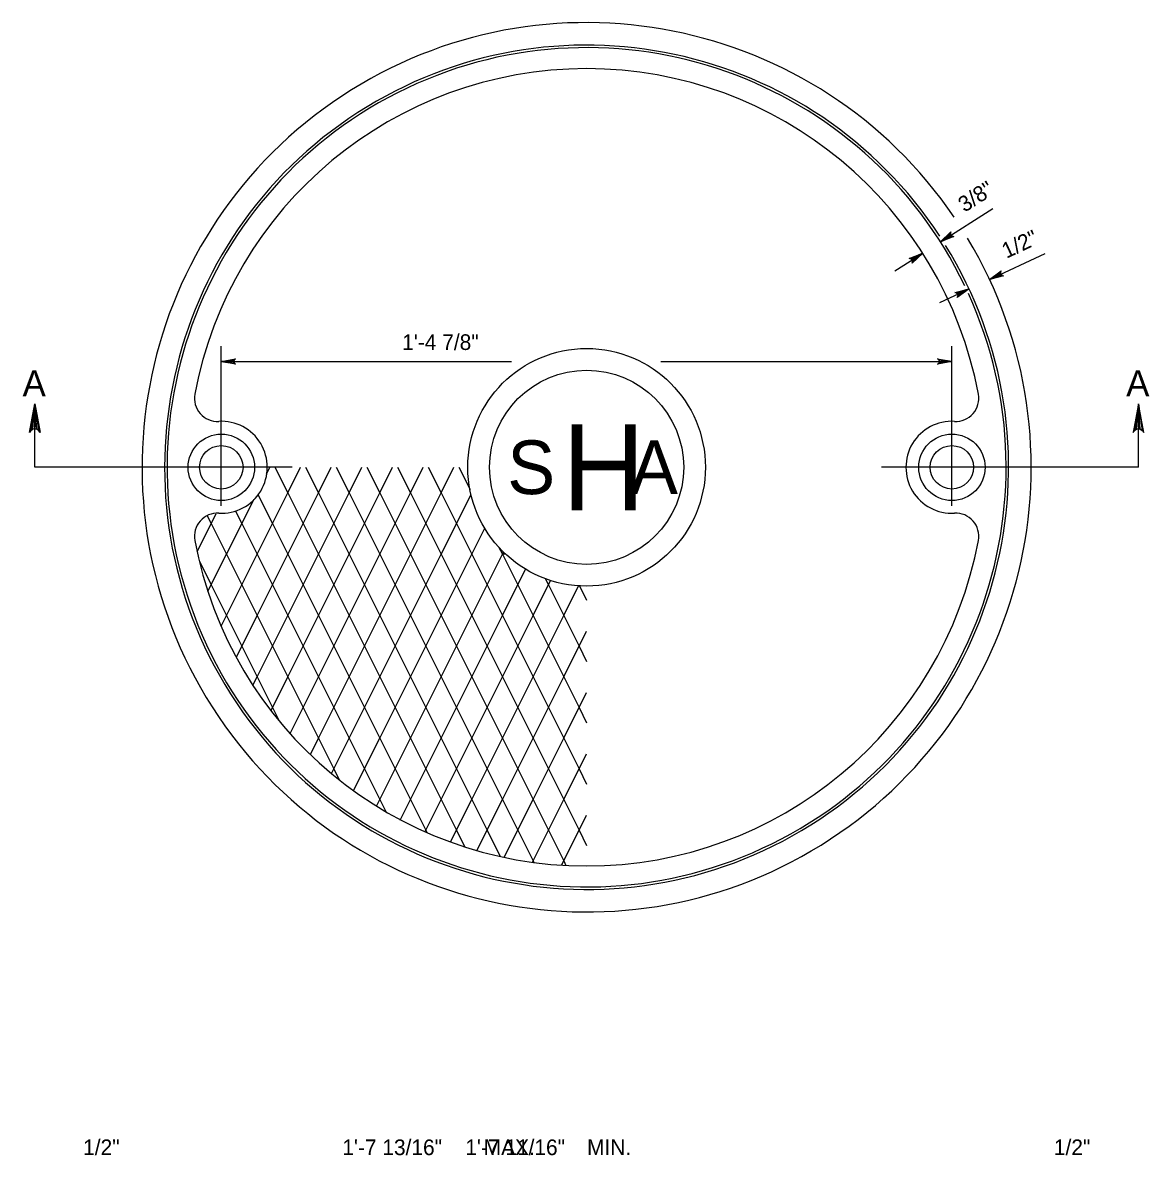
# Model space of a CAD drawing. Extents: x 2.36 to 8.41, y -8.97 to 0.21.
# Drawn here: x 2.563 to 6.887, y -4.133 to 0.213 of the extents above; entities that cross this region are included whole.
import ezdxf

# ---------------------------------------------------------------- set-up
doc = ezdxf.new("R2010")
doc.units = 0
for name, color, linetype in [('DETL-DIMS', 7, 'Continuous'), ('DETL-LINE', 7, 'Continuous'), ('DETL-NOTE', 7, 'Continuous'), ('DETL-PATT', 7, 'Continuous')]:
    doc.layers.add(name, color=color, linetype=linetype)

msp = doc.modelspace()

# ---------------------------------------------------------------- linework, layer by layer
at = {"layer": 'DETL-DIMS'}
for p, q in [((6.0855, -0.628), (6.2865, -0.5)), ((5.9113, -0.739), (6.0177, -0.6712)), ((6.2739, -0.772), (6.4871, -0.6725)), ((6.084, -0.8605), (6.1955, -0.8085)), ((3.3259, -1.6412), (3.3259, -1.0281)), ((6.1298, -1.6412), (6.1298, -1.0281)), ((3.3259, -1.087), (4.4391, -1.087)), ((5.0126, -1.087), (6.1298, -1.087)), ((2.6102, -1.4929), (2.6102, -1.25)), ((6.8455, -1.4929), (6.8455, -1.25)), ((3.5984, -1.4929), (2.6102, -1.4929)), ((6.8455, -1.4929), (5.8598, -1.4929))]:
    msp.add_line(p, q, dxfattribs=at)
for points in [[(6.0855, -0.628), (6.1262, -0.5899), (6.1242, -0.5946), (6.1243, -0.5989), (6.1258, -0.6023), (6.1283, -0.6051), (6.1321, -0.607), (6.1372, -0.6072), (6.0855, -0.628), (6.1321, -0.607), (6.1283, -0.6051), (6.0855, -0.628), (6.1258, -0.6023), (6.1243, -0.5989), (6.0855, -0.628), (6.1242, -0.5946)], [(6.0177, -0.6712), (5.977, -0.7093), (5.979, -0.7045), (5.9789, -0.7003), (5.9774, -0.6968), (5.9749, -0.6941), (5.9711, -0.6921), (5.966, -0.6919), (6.0177, -0.6712), (5.9711, -0.6921), (5.9749, -0.6941), (6.0177, -0.6712), (5.9774, -0.6968), (5.9789, -0.7003), (6.0177, -0.6712), (5.979, -0.7045)], [(6.2739, -0.772), (6.3192, -0.7395), (6.3167, -0.7439), (6.3162, -0.7482), (6.3172, -0.7518), (6.3193, -0.7548), (6.3229, -0.7572), (6.3279, -0.7581), (6.2739, -0.772), (6.3229, -0.7572), (6.3193, -0.7548), (6.2739, -0.772), (6.3172, -0.7518), (6.3162, -0.7482), (6.2739, -0.772), (6.3167, -0.7439)], [(6.1955, -0.8085), (6.1501, -0.841), (6.1527, -0.8366), (6.1531, -0.8323), (6.1522, -0.8287), (6.15, -0.8257), (6.1465, -0.8233), (6.1414, -0.8224), (6.1955, -0.8085), (6.1465, -0.8233), (6.15, -0.8257), (6.1955, -0.8085), (6.1522, -0.8287), (6.1531, -0.8323), (6.1955, -0.8085), (6.1527, -0.8366)], [(3.3259, -1.087), (3.3807, -1.0767), (3.3765, -1.0796), (3.3743, -1.0833), (3.3737, -1.087), (3.3743, -1.0906), (3.3765, -1.0943), (3.3807, -1.0972), (3.3259, -1.087), (3.3765, -1.0943), (3.3743, -1.0906), (3.3259, -1.087), (3.3737, -1.087), (3.3743, -1.0833), (3.3259, -1.087), (3.3765, -1.0796)], [(6.1298, -1.087), (6.075, -1.0972), (6.0792, -1.0943), (6.0814, -1.0906), (6.082, -1.087), (6.0814, -1.0833), (6.0792, -1.0796), (6.075, -1.0767), (6.1298, -1.087), (6.0792, -1.0796), (6.0814, -1.0833), (6.1298, -1.087), (6.082, -1.087), (6.0814, -1.0906), (6.1298, -1.087), (6.0792, -1.0943)], [(2.6102, -1.25), (2.6308, -1.3596), (2.6249, -1.3512), (2.6175, -1.3468), (2.6102, -1.3456), (2.6028, -1.3468), (2.5955, -1.3512), (2.5896, -1.3596), (2.6102, -1.25), (2.5955, -1.3512), (2.6028, -1.3468), (2.6102, -1.25), (2.6102, -1.3456), (2.6175, -1.3468), (2.6102, -1.25), (2.6249, -1.3512)], [(6.8455, -1.25), (6.8249, -1.3596), (6.8308, -1.3512), (6.8381, -1.3468), (6.8455, -1.3456), (6.8528, -1.3468), (6.8602, -1.3512), (6.8661, -1.3596), (6.8455, -1.25), (6.8602, -1.3512), (6.8528, -1.3468), (6.8455, -1.25), (6.8455, -1.3456), (6.8381, -1.3468), (6.8455, -1.25), (6.8308, -1.3512)]]:
    msp.add_lwpolyline(points, dxfattribs=at)
at = {"layer": 'DETL-LINE'}
for centre, radius in [((4.7278, -1.4929), 0.4559), ((4.7278, -1.4929), 0.3725), ((3.3259, -1.4929), 0.1275), ((6.1298, -1.4929), 0.1275), ((3.3259, -1.4929), 0.0833), ((6.1298, -1.4929), 0.0833)]:
    msp.add_circle(centre, radius, dxfattribs=at)
for centre, radius, start, end in [((4.7278, -1.4929), 1.7059, 34.2067, 31.0349), ((4.7278, -1.4929), 1.6194, 33.1799, 31.7212), ((4.7278, -1.4929), 1.6097, 25.6326, 24.4561), ((4.7278, -1.4929), 1.5294, 10.5671, 169.4329), ((3.3111, -1.2286), 0.0882, 169.4329, 273.1996), ((6.1446, -1.2286), 0.0882, 266.8004, 10.5671), ((3.3259, -1.4929), 0.1765, 266.8004, 93.1996), ((6.1298, -1.4929), 0.1765, 86.8004, 273.1996), ((3.3111, -1.7572), 0.0882, 86.8004, 190.5671), ((6.1446, -1.7572), 0.0882, 349.4329, 93.1996), ((4.7278, -1.4929), 1.5294, 190.5671, 349.4329)]:
    msp.add_arc(centre, radius, start, end, dxfattribs=at)
at = {"layer": 'DETL-PATT'}
for p, q in [((3.4996, -1.519), (3.5126, -1.4929)), ((3.5319, -1.4929), (3.5811, -1.5912)), ((3.5811, -1.5912), (3.6303, -1.4929)), ((3.6496, -1.4929), (3.6988, -1.5912)), ((3.6988, -1.5912), (3.7479, -1.4929)), ((3.7672, -1.4929), (3.8164, -1.5912)), ((3.8164, -1.5912), (3.8656, -1.4929)), ((3.8849, -1.4929), (3.934, -1.5912)), ((3.934, -1.5912), (3.9832, -1.4929)), ((4.0025, -1.4929), (4.0517, -1.5912)), ((4.0517, -1.5912), (4.1008, -1.4929)), ((4.1202, -1.4929), (4.1693, -1.5912)), ((4.1693, -1.5912), (4.2185, -1.4929)), ((4.2378, -1.4929), (4.2805, -1.5782)), ((3.4635, -1.8265), (3.5811, -1.5912)), ((3.4665, -1.5974), (3.5223, -1.7089)), ((3.5811, -1.8265), (3.6988, -1.5912)), ((3.5811, -1.5912), (3.6399, -1.7089)), ((3.6988, -1.8265), (3.8164, -1.5912)), ((3.6988, -1.5912), (3.7576, -1.7089)), ((3.8164, -1.8265), (3.934, -1.5912)), ((3.8164, -1.5912), (3.8752, -1.7089)), ((3.934, -1.8265), (4.0517, -1.5912)), ((3.934, -1.5912), (3.9929, -1.7089)), ((4.0517, -1.8265), (4.1693, -1.5912)), ((4.0517, -1.5912), (4.1105, -1.7089)), ((4.1693, -1.5912), (4.2282, -1.7089)), ((4.1693, -1.8265), (4.2842, -1.5968)), ((3.3458, -1.8265), (3.4516, -1.6148)), ((3.2335, -1.8158), (3.3057, -1.6714)), ((3.2719, -1.6788), (3.287, -1.7089)), ((3.3796, -1.6588), (3.4046, -1.7089)), ((3.287, -1.7089), (3.3458, -1.8265)), ((3.4046, -1.7089), (3.4635, -1.8265)), ((3.5223, -1.7089), (3.5811, -1.8265)), ((3.6399, -1.7089), (3.6988, -1.8265)), ((3.7576, -1.7089), (3.8164, -1.8265)), ((3.8752, -1.7089), (3.934, -1.8265)), ((3.9929, -1.7089), (4.0517, -1.8265)), ((4.1105, -1.7089), (4.1693, -1.8265)), ((4.2282, -1.7089), (4.287, -1.8265)), ((4.287, -1.8265), (4.3372, -1.726)), ((4.3915, -1.8003), (4.4046, -1.8265)), ((4.4046, -1.8265), (4.409, -1.8177)), ((3.2416, -1.8534), (3.287, -1.9442)), ((3.2748, -1.9685), (3.3458, -1.8265)), ((3.3458, -2.0618), (3.4635, -1.8265)), ((3.3458, -1.8265), (3.4046, -1.9442)), ((3.4635, -2.0618), (3.5811, -1.8265)), ((3.4635, -1.8265), (3.5223, -1.9442)), ((3.5811, -2.0618), (3.6988, -1.8265)), ((3.5811, -1.8265), (3.6399, -1.9442)), ((3.6988, -2.0618), (3.8164, -1.8265)), ((3.6988, -1.8265), (3.7576, -1.9442)), ((3.8164, -2.0618), (3.934, -1.8265)), ((3.8164, -1.8265), (3.8752, -1.9442)), ((3.934, -2.0618), (4.0517, -1.8265)), ((3.934, -1.8265), (3.9929, -1.9442)), ((4.0517, -2.0618), (4.1693, -1.8265)), ((4.0517, -1.8265), (4.1105, -1.9442)), ((4.1693, -2.0618), (4.287, -1.8265)), ((4.1693, -1.8265), (4.2282, -1.9442)), ((4.287, -2.0618), (4.4046, -1.8265)), ((4.287, -1.8265), (4.3458, -1.9442)), ((4.4046, -1.8265), (4.4635, -1.9442)), ((4.4184, -1.8265), (4.4046, -1.8265)), ((4.4046, -2.0618), (4.4939, -1.8833)), ((3.287, -1.9442), (3.3458, -2.0618)), ((3.4046, -1.9442), (3.4635, -2.0618)), ((3.5223, -1.9442), (3.5811, -2.0618)), ((3.6399, -1.9442), (3.6988, -2.0618)), ((3.7576, -1.9442), (3.8164, -2.0618)), ((3.8752, -1.9442), (3.934, -2.0618)), ((3.9929, -1.9442), (4.0517, -2.0618)), ((4.1105, -1.9442), (4.1693, -2.0618)), ((4.2282, -1.9442), (4.287, -2.0618)), ((4.3458, -1.9442), (4.4046, -2.0618)), ((4.4635, -1.9442), (4.5223, -2.0618)), ((4.5223, -2.0618), (4.5896, -1.9272)), ((4.5688, -1.9196), (4.5811, -1.9442)), ((4.5811, -1.9442), (4.6399, -2.0618)), ((4.6399, -2.0618), (4.6972, -1.9473)), ((4.7004, -1.9475), (4.7278, -2.0023)), ((3.3254, -2.1026), (3.3458, -2.0618)), ((3.3458, -2.0618), (3.4046, -2.1795)), ((3.3837, -2.2214), (3.4635, -2.0618)), ((3.4635, -2.2971), (3.5811, -2.0618)), ((3.4635, -2.0618), (3.5223, -2.1795)), ((3.5811, -2.2971), (3.6988, -2.0618)), ((3.5811, -2.0618), (3.6399, -2.1795)), ((3.6988, -2.2971), (3.8164, -2.0618)), ((3.6988, -2.0618), (3.7576, -2.1795)), ((3.8164, -2.2971), (3.934, -2.0618)), ((3.8164, -2.0618), (3.8752, -2.1795)), ((3.934, -2.2971), (4.0517, -2.0618)), ((3.934, -2.0618), (3.9929, -2.1795)), ((4.0517, -2.2971), (4.1693, -2.0618)), ((4.0517, -2.0618), (4.1105, -2.1795)), ((4.1693, -2.2971), (4.287, -2.0618)), ((4.1693, -2.0618), (4.2282, -2.1795)), ((4.287, -2.2971), (4.4046, -2.0618)), ((4.287, -2.0618), (4.3458, -2.1795)), ((4.4046, -2.2971), (4.5223, -2.0618)), ((4.4046, -2.0618), (4.4635, -2.1795)), ((4.5223, -2.2971), (4.6399, -2.0618)), ((4.5223, -2.0618), (4.5811, -2.1795)), ((4.6399, -2.0618), (4.6988, -2.1795)), ((4.6399, -2.2971), (4.7278, -2.1213)), ((3.4046, -2.1795), (3.4635, -2.2971)), ((3.5223, -2.1795), (3.5811, -2.2971)), ((3.6399, -2.1795), (3.6988, -2.2971)), ((3.7576, -2.1795), (3.8164, -2.2971)), ((3.8752, -2.1795), (3.934, -2.2971)), ((3.9929, -2.1795), (4.0517, -2.2971)), ((4.1105, -2.1795), (4.1693, -2.2971)), ((4.2282, -2.1795), (4.287, -2.2971)), ((4.3458, -2.1795), (4.4046, -2.2971)), ((4.4635, -2.1795), (4.5223, -2.2971)), ((4.5811, -2.1795), (4.6399, -2.2971)), ((4.6988, -2.1795), (4.7278, -2.2376)), ((3.4475, -2.329), (3.4635, -2.2971)), ((3.4635, -2.2971), (3.5223, -2.4147)), ((3.5167, -2.4259), (3.5811, -2.2971)), ((3.5811, -2.2971), (3.6399, -2.4147)), ((3.59, -2.5145), (3.6988, -2.2971)), ((3.6988, -2.5324), (3.8164, -2.2971)), ((3.6988, -2.2971), (3.7576, -2.4147)), ((3.8164, -2.5324), (3.934, -2.2971)), ((3.8164, -2.2971), (3.8752, -2.4147)), ((3.934, -2.5324), (4.0517, -2.2971)), ((3.934, -2.2971), (3.9929, -2.4147)), ((4.0517, -2.5324), (4.1693, -2.2971)), ((4.0517, -2.2971), (4.1105, -2.4147)), ((4.1693, -2.5324), (4.287, -2.2971)), ((4.1693, -2.2971), (4.2282, -2.4147)), ((4.287, -2.5324), (4.4046, -2.2971)), ((4.287, -2.2971), (4.3458, -2.4147)), ((4.4046, -2.5324), (4.5223, -2.2971)), ((4.4046, -2.2971), (4.4635, -2.4147)), ((4.5223, -2.5324), (4.6399, -2.2971)), ((4.5223, -2.2971), (4.5811, -2.4147)), ((4.6399, -2.2971), (4.6988, -2.4147)), ((4.6399, -2.5324), (4.7278, -2.3566)), ((3.5223, -2.4147), (3.5475, -2.4651)), ((3.6399, -2.4147), (3.6988, -2.5324)), ((3.7576, -2.4147), (3.8164, -2.5324)), ((3.8752, -2.4147), (3.934, -2.5324)), ((3.9929, -2.4147), (4.0517, -2.5324)), ((4.1105, -2.4147), (4.1693, -2.5324)), ((4.2282, -2.4147), (4.287, -2.5324)), ((4.3458, -2.4147), (4.4046, -2.5324)), ((4.4635, -2.4147), (4.5223, -2.5324)), ((4.5811, -2.4147), (4.6399, -2.5324)), ((4.6988, -2.4147), (4.7278, -2.4729)), ((3.6676, -2.5947), (3.6988, -2.5324)), ((3.6988, -2.5324), (3.7576, -2.65)), ((3.749, -2.6673), (3.8164, -2.5324)), ((3.8164, -2.5324), (3.8752, -2.65)), ((3.8337, -2.7331), (3.934, -2.5324)), ((3.934, -2.7677), (4.0517, -2.5324)), ((3.934, -2.5324), (3.9929, -2.65)), ((4.0517, -2.7677), (4.1693, -2.5324)), ((4.0517, -2.5324), (4.1105, -2.65)), ((4.1693, -2.7677), (4.287, -2.5324)), ((4.1693, -2.5324), (4.2282, -2.65)), ((4.287, -2.7677), (4.4046, -2.5324)), ((4.287, -2.5324), (4.3458, -2.65)), ((4.4046, -2.7677), (4.5223, -2.5324)), ((4.4046, -2.5324), (4.4635, -2.65)), ((4.5223, -2.7677), (4.6399, -2.5324)), ((4.5223, -2.5324), (4.5811, -2.65)), ((4.6399, -2.5324), (4.6988, -2.65)), ((4.6399, -2.7677), (4.7278, -2.5919)), ((3.7576, -2.65), (3.7784, -2.6917)), ((3.8752, -2.65), (3.934, -2.7677)), ((3.9929, -2.65), (4.0517, -2.7677)), ((4.1105, -2.65), (4.1693, -2.7677)), ((4.2282, -2.65), (4.287, -2.7677)), ((4.3458, -2.65), (4.4046, -2.7677)), ((4.4635, -2.65), (4.5223, -2.7677)), ((4.5811, -2.65), (4.6399, -2.7677)), ((4.6988, -2.65), (4.7278, -2.7082)), ((3.9216, -2.7925), (3.934, -2.7677)), ((3.934, -2.7677), (3.9569, -2.8135)), ((4.0124, -2.8463), (4.0517, -2.7677)), ((4.0517, -2.7677), (4.1105, -2.8853)), ((4.108, -2.8904), (4.1693, -2.7677)), ((4.1693, -2.7677), (4.2282, -2.8853)), ((4.2058, -2.93), (4.287, -2.7677)), ((4.287, -2.7677), (4.3458, -2.8853)), ((4.3069, -2.9632), (4.4046, -2.7677)), ((4.4046, -2.7677), (4.4635, -2.8853)), ((4.4117, -2.9888), (4.5223, -2.7677)), ((4.5223, -3.003), (4.6399, -2.7677)), ((4.5223, -2.7677), (4.5811, -2.8853)), ((4.6399, -2.7677), (4.6988, -2.8853)), ((4.6399, -3.003), (4.7278, -2.8271)), ((4.1105, -2.8853), (4.1145, -2.8933)), ((4.2282, -2.8853), (4.2596, -2.9483)), ((4.3458, -2.8853), (4.396, -2.9858)), ((4.4635, -2.8853), (4.5223, -3.003)), ((4.5811, -2.8853), (4.6399, -3.003)), ((4.6988, -2.8853), (4.7278, -2.9435)), ((4.52, -3.0075), (4.5223, -3.003)), ((4.5223, -3.003), (4.5249, -3.0082)), ((4.6319, -3.019), (4.6399, -3.003)), ((4.6399, -3.003), (4.6485, -3.0201))]:
    msp.add_line(p, q, dxfattribs=at)

# ---------------------------------------------------------------- texts
at = {"layer": 'DETL-LINE'}
for s, height, p in [('H', 0.3294, (4.6345, -1.6576)), ('S', 0.2059, (4.4234, -1.5958)), ('A', 0.2059, (4.8948, -1.5958))]:
    msp.add_text(s, height=height, dxfattribs=at).set_placement(p)
at = {"layer": 'DETL-NOTE'}
for s, rotation, p in [('3/8"', 32.5, (6.1781, -0.5167)), ('1/2"', 25, (6.3389, -0.693))]:
    msp.add_text(s, height=0.06, rotation=rotation, dxfattribs=at).set_placement(p)
for s, height, p in [('1\'-4 7/8"', 0.06, (4.0201, -1.0428)), ('A', 0.1, (2.5632, -1.2206)), ('A', 0.1, (6.7985, -1.2206)), ('1/2"', 0.06, (2.7956, -4.1318)), ('1\'-7 13/16"    1\'-7 11/16"', 0.06, (3.7903, -4.1318)), ('MAX.         MIN.', 0.06, (4.3329, -4.1318)), ('1/2"', 0.06, (6.5211, -4.1318))]:
    msp.add_text(s, height=height, dxfattribs=at).set_placement(p)

doc.saveas('drawing.dxf')
